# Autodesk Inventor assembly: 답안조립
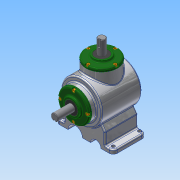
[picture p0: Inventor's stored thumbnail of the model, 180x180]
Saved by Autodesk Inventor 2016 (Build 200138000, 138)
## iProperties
Created: 2018-08
Part Number: 답안조립
Material: 일반
Document SubType Name: Assembly
Designer: Administrator
Author: Administrator
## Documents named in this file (14)
- C:\Users\Administrator\Desktop\480807V1007\답안조립.iam
- C:\Users\Administrator\Desktop\480807V1007\본체.ipt
- C:\Users\Administrator\Desktop\480807V1007\메인 축.ipt
- 메인 축.ipt
- C:\Users\Administrator\Desktop\480807V1007\키 5x5.ipt
- C:\Users\Administrator\Desktop\480807V1007\베어링 6203.ipt
- C:\Users\Administrator\Desktop\480807V1007\커버.ipt
- C:\Users\Administrator\Desktop\480807V1007\오일실 17 32 8.ipt
- C:\Users\Administrator\Desktop\480807V1007\메인 베벨기어.ipt
- C:\Users\Administrator\Desktop\480807V1007\서브 축.ipt
- 서브 축.ipt
- C:\Users\Administrator\Desktop\480807V1007\키 4x4.ipt
- C:\Users\Administrator\Desktop\480807V1007\서브 베벨기어.ipt
- C:\Users\Administrator\Desktop\480807V1007\볼트 M4.ipt
